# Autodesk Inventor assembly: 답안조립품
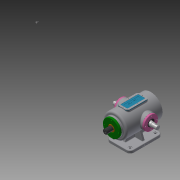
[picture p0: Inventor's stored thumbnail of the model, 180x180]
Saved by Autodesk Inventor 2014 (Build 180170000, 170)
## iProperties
Created: 2021-11
Part Number: 답안조립품
Document SubType Name: Assembly
Designer: kb542
Author: kb542
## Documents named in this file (14)
- C:\Users\kb542\Desktop\711106V1001\답안조립품.iam
- C:\Users\kb542\Desktop\711106V1001\본체.ipt
- C:\Users\kb542\Desktop\711106V1001\베어링 6205.ipt
- 베어링 6205.ipt
- C:\Users\kb542\Desktop\711106V1001\볼트 M4x0.7.ipt
- C:\Users\kb542\Desktop\711106V1001\부시.ipt
- C:\Users\kb542\Desktop\711106V1001\상부커버.ipt
- C:\Users\kb542\Desktop\711106V1001\슬라이드 커버.ipt
- C:\Users\kb542\Desktop\711106V1001\슬라이드.ipt
- C:\Users\kb542\Desktop\711106V1001\오일실.ipt
- 오일실.ipt
- C:\Users\kb542\Desktop\711106V1001\육각머리볼트 M4.ipt
- C:\Users\kb542\Desktop\711106V1001\축 커버.ipt
- C:\Users\kb542\Desktop\711106V1001\편심축.ipt
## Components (8 placed, 1 different names)
1. M4x0.7:1
2. M4x0.7:2
3. M4x0.7:3
4. M4x0.7:4
5. M4x0.7:5
6. M4x0.7:6
7. M4x0.7:7
8. M4x0.7:8
## Named parameters: d27_d26 = 0, d28_d18 = 0, d29_d19 = 0, d30_d20 = 0, d31_d21 = 0, d32_d22 = 0, d33_d23 = 0, d34_d24 = 0, d35_d25 = 0
